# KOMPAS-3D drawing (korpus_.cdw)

Views: Вид 1
Referenced files: Чертеж1.cdw
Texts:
  Корпус
  Текст на чертеже
  Размерные надписи
  Шероховатость
  Линия-выноска #1
  Линия-выноска #2
  Линия-выноска #3
  Отклонения формы и база
  Заголовок таблицы
  Ячейка таблицы
  Стрелка вида
  Обозначение изменения
  Фигурная скобка
  Номер узла
  Марка координационной оси
  VRCB
  Выносная надпись
  Обозначение узла
  Марка/позиционное обозначение с линией-выноской
  Марка/позиционное обозначение на линии
  Марка/позиционное обозначение без линии-выноски
  Symbol type A
  Чугун СЧ15 ГОСТ 1412-85
Dimensions and other numbers on the sheet: 61 00 Т 01; 7; 8; 10; 25; 3.2; 2.5; 15; 160; 6.3; 1; 117; 1:1; 61 00 Т 01-; 0; 2; 3; 4; 5; 6; 9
